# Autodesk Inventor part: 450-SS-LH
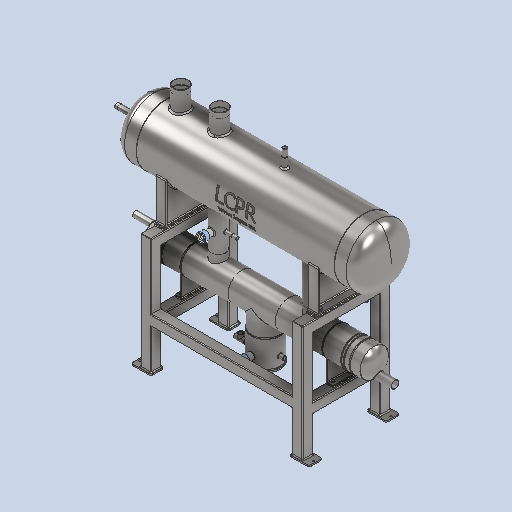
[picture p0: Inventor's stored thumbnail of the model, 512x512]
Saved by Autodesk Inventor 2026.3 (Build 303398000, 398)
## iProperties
Created: 2026-05
Part Number: 450-SS-LH
Material: Generic
Document SubType Name: Modeling
Designer: rva
Density: 1 g/cm^3
Appearance: Default
Author: rva
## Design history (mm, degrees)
derived "450-SS-LH.iam"
body "Solid1"
node "Nylon Heat Tranfer Spacer 175x50.ipt:1"
node "Nylon Heat Tranfer Spacer 175x50.ipt:2"
node "Nylon Heat Tranfer Spacer 460x75.ipt:1"
node "Nylon Heat Tranfer Spacer 460x75.ipt:2"
node "Sub-SS-200-100-1370-48-10-50-40-WELD.iam:1::LCPR-200 SS Blan"
node "Sub-SS-200-100-1370-48-10-50-40-WELD.iam:1::SS-200 mm Subcoo"
node "Sub-SS-200-100-1370-48-10-50-40-WELD.iam:1::SS-200 mm Subcoo"
node "Sub-SS-200-100-1370-48-10-50-40-WELD.iam:1::DIN 2462 Tube 10"
node "Sub-SS-200-100-1370-48-10-50-40-WELD.iam:1::DIN 2462 Tube 10"
node "Sub-SS-200-100-1370-48-10-50-40-WELD.iam:1::DIN 2462 Tube 10"
node "Sub-SS-200-100-1370-48-10-50-40-WELD.iam:1::DIN 2462 Tube 10"
node "Sub-SS-200-100-1370-48-10-50-40-WELD.iam:1::H1100-R.ipt:1"
node "Sub-SS-200-100-1370-48-10-50-40-WELD.iam:1::H1100-R.ipt:2"
node "Sub-SS-200-100-1370-48-10-50-40-WELD.iam:1::1-2 Inch NPT Soc"
node "Sub-SS-200-100-1370-48-10-50-40-WELD.iam:1::3-4 Inch NPT Soc"
node "Sub-SS-200-100-1370-48-10-50-40-WELD.iam:1::1-2 Inch NPT Soc"
node "Sub-SS-200-100-1370-48-10-50-40-WELD.iam:1::Welds"
node "LCPR-SS-450-1500-100-WELD.iam:1::H1100-R.ipt:1"
node "LCPR-SS-450-1500-100-WELD.iam:1::450 mm SS Dome Cap.ipt:1"
node "LCPR-SS-450-1500-100-WELD.iam:1::450 mm SS Dome Cap.ipt:2"
node "LCPR-SS-450-1500-100-WELD.iam:1::Welds"
node "AS 1112 (2) - Metric M16  Type 10:1"
node "AS 1237 (4.1) 16 mm:1"
node "AS 1237 (4.1) 16 mm:2"
node "AS 1112 (2) - Metric M16  Type 10:2"
node "AS 1237 (4.1) 16 mm:3"
node "AS 1237 (4.1) 16 mm:4"
node "AS 1252 - Metric M16 x 120:2"
node "AS 1112 (2) - Metric M16  Type 10:3"
node "AS 1237 (4.1) 16 mm:5"
node "AS 1237 (4.1) 16 mm:6"
node "AS 1252 - Metric M16 x 120:3"
node "AS 1112 (2) - Metric M16  Type 10:4"
node "AS 1237 (4.1) 16 mm:7"
node "AS 1237 (4.1) 16 mm:8"
node "AS 1252 - Metric M16 x 120:4"
node "AS 1112 (2) - Metric M10  Type 10:1"
node "AS 1237 (D1) 10 mm:1"
node "AS 1237 (D1) 10 mm:2"
node "AS 1111 - Metric M10 x 120:1"
node "AS 1112 (2) - Metric M10  Type 10:2"
feature "萀봈"
node "AS 1237 (D1) 10 mm:3"
node "AS 1237 (D1) 10 mm:4"
node "AS 1111 - Metric M10 x 120:2"
node "AS 1112 (2) - Metric M10  Type 10:3"
node "AS 1237 (D1) 10 mm:5"
node "AS 1237 (D1) 10 mm:6"
node "AS 1111 - Metric M10 x 120:3"
node "AS 1112 (2) - Metric M10  Type 10:4"
node "AS 1237 (D1) 10 mm:7"
node "AS 1237 (D1) 10 mm:8"
node "AS 1111 - Metric M10 x 120:4"
node "Welds"
node "AS 1252 - Metric M16 x 120:5"
node "450-SS-LH.iam_Bodies"
